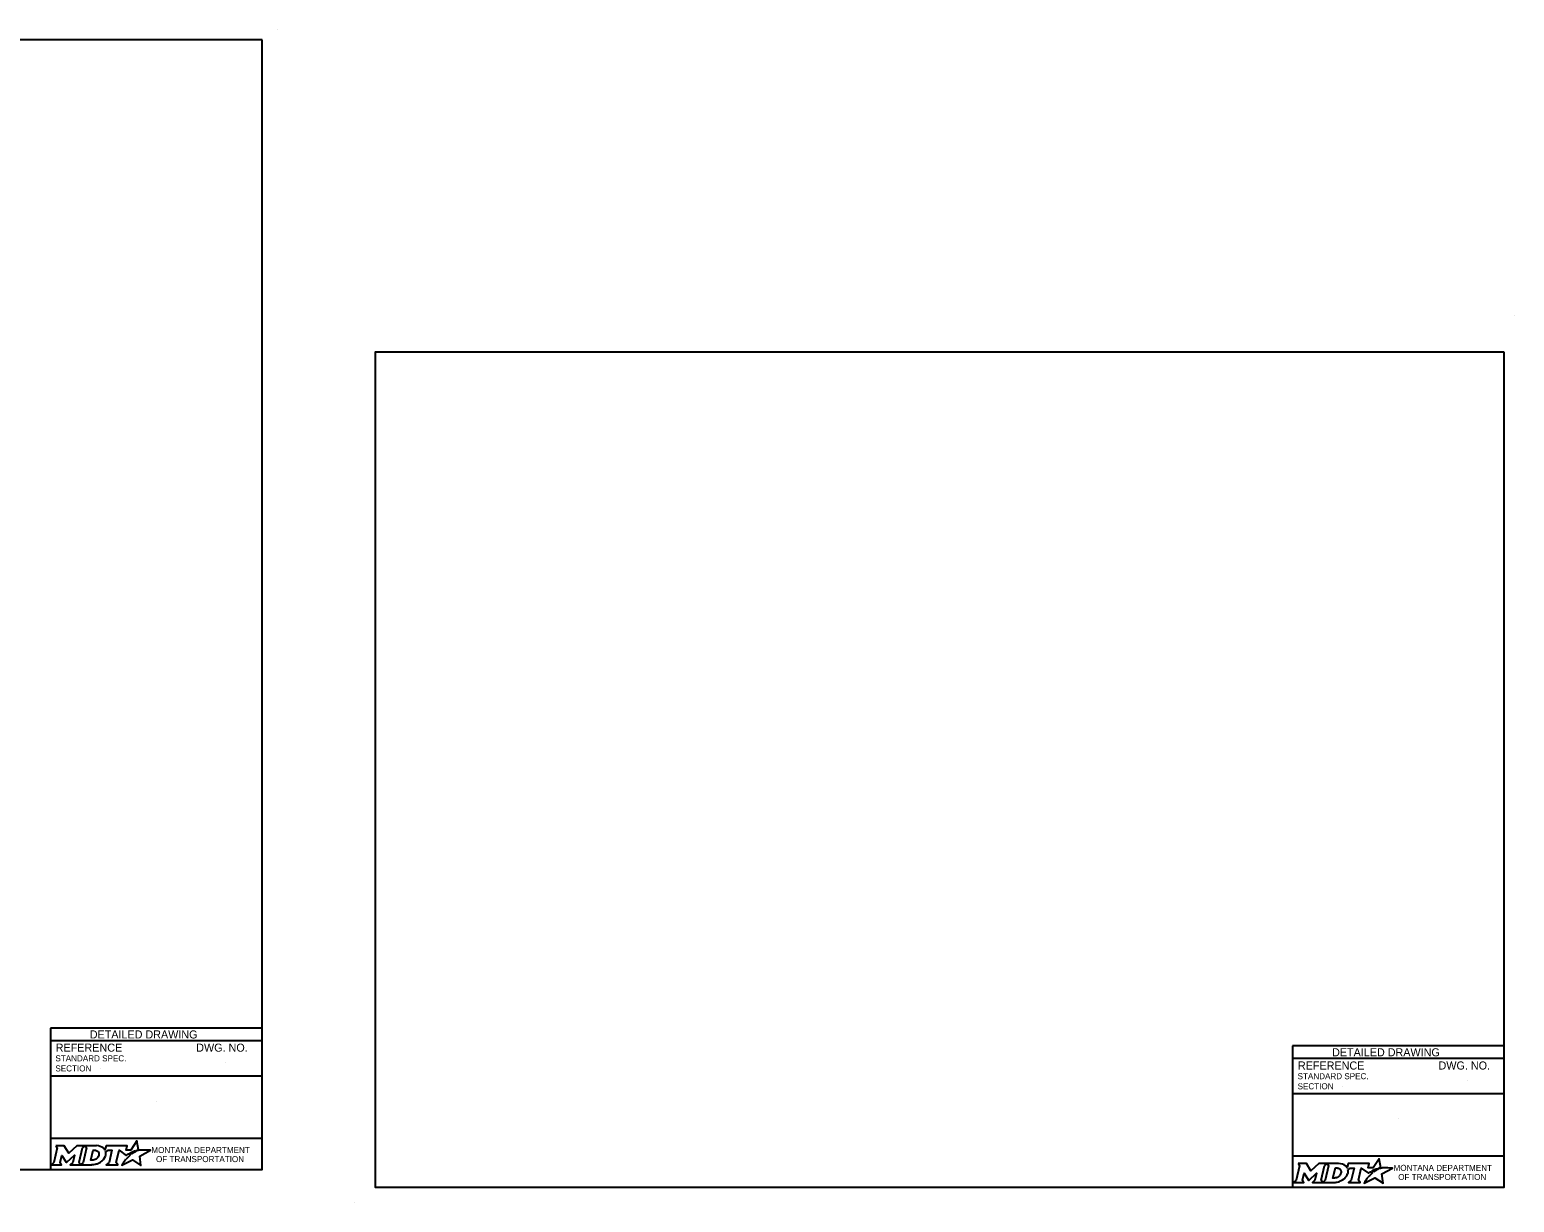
# Model space of a CAD drawing. Extents: x 49991.4 to 50021, y 49987.6 to 50011.4.
# Drawn here: x 50006.31 to 50021.04, y 49999.74 to 50011.36 of the extents above; entities that cross this region are included whole.
import ezdxf

# ---------------------------------------------------------------- set-up
doc = ezdxf.new("R2010")
doc.units = 0
for name, color, linetype in [('Default', 7, 'Continuous'), ('Level 1', 7, 'Continuous'), ('Level 2', 7, 'Continuous'), ('Level 4', 7, 'Continuous')]:
    doc.layers.add(name, color=color, linetype=linetype)

msp = doc.modelspace()

# ---------------------------------------------------------------- linework, layer by layer
at = {"layer": 'Default'}
for points in [[(50018.893, 50000.121), (50018.907, 50000.097), (50018.874, 49999.954), (50018.848, 49999.931), (50018.95, 49999.931), (50018.936, 49999.954), (50018.952, 50000.024), (50018.996, 49999.955), (50019.002, 49999.955), (50019.077, 50000.025), (50019.06, 49999.954), (50019.035, 49999.932), (50019.137, 49999.932), (50019.123, 49999.955), (50019.156, 50000.097)], [(50019.156, 50000.097), (50019.182, 50000.121), (50019.099, 50000.121), (50019.02, 50000.048), (50018.975, 50000.12), (50018.893, 50000.121)], [(50019.295, 50000.121), (50019.182, 50000.121), (50019.196, 50000.098), (50019.163, 49999.954), (50019.137, 49999.932), (50019.248, 49999.932)], [(50019.319, 50000.034), (50019.318, 50000.026), (50019.315, 50000.017), (50019.311, 50000.008), (50019.305, 50000.001), (50019.299, 49999.994), (50019.291, 49999.988), (50019.282, 49999.983), (50019.273, 49999.979), (50019.264, 49999.977), (50019.255, 49999.976), (50019.239, 49999.976), (50019.263, 50000.076), (50019.279, 50000.076), (50019.286, 50000.075), (50019.294, 50000.073), (50019.301, 50000.07), (50019.307, 50000.066), (50019.311, 50000.061), (50019.315, 50000.055), (50019.318, 50000.049), (50019.319, 50000.042), (50019.32, 50000.038), (50019.319, 50000.034)], [(50019.7, 50000.068), (50019.69, 50000.074), (50019.702, 50000.076), (50019.713, 50000.078), (50019.696, 50000.168), (50019.636, 50000.077), (50019.589, 50000.076), (50019.599, 50000.12), (50019.39, 50000.121), (50019.38, 50000.078), (50019.374, 50000.086)], [(50019.387, 50000.062), (50019.411, 50000.075), (50019.448, 50000.075), (50019.42, 49999.954), (50019.392, 49999.931), (50019.508, 49999.931), (50019.491, 49999.954), (50019.52, 50000.075), (50019.591, 50000.023), (50019.612, 50000.038), (50019.632, 50000.027)], [(50019.576, 49999.971), (50019.561, 49999.947), (50019.556, 49999.939), (50019.55, 49999.931), (50019.548, 49999.926), (50019.653, 49999.979), (50019.737, 49999.924), (50019.724, 50000.017), (50019.831, 50000.075), (50019.782, 50000.076), (50019.751, 50000.077), (50019.731, 50000.077), (50019.724, 50000.075), (50019.719, 50000.074), (50019.711, 50000.072), (50019.7, 50000.068)], [(50019.65, 50000.04), (50019.648, 50000.039), (50019.629, 50000.048), (50019.639, 50000.054), (50019.644, 50000.056), (50019.652, 50000.06), (50019.658, 50000.063), (50019.666, 50000.066), (50019.673, 50000.068), (50019.685, 50000.061), (50019.681, 50000.059), (50019.676, 50000.056), (50019.672, 50000.054), (50019.667, 50000.051), (50019.665, 50000.05), (50019.662, 50000.049), (50019.66, 50000.047), (50019.658, 50000.046), (50019.655, 50000.044), (50019.652, 50000.042), (50019.65, 50000.04)], [(50019.293, 49999.939), (50019.302, 49999.942), (50019.315, 49999.947), (50019.335, 49999.958)], [(50019.59, 49999.987), (50019.59, 49999.987)]]:
    msp.add_lwpolyline(points, dxfattribs=at)
for centre, radius, start, end in [((50019.274, 50000.059), 0.118, 300.9103, 339.1383), ((50019.319, 50000.042), 0.0709, 339.5329, 15.8582)]:
    msp.add_arc(centre, radius, start, end, dxfattribs=at)
for centre, major_axis, ratio, start_param, end_param in [((50019.293, 50000.073), (0.0834, -0.0037), 0.568097, 0.61298, 1.570796), ((50019.349, 50000.081), (0.0361, -0.0295), 0.469099, 1.225588, 1.570796), ((50019.248, 50000.08), (0, 0.148), 0.987302, 3.139398, 3.456847), ((50019.583, 49999.979), (-0.00694, -0.00806), 0.008222, 0, 3.137361), ((50019.6, 49999.997), (-0.0098, -0.0102), 0.016458, 3.141593, 6.279097), ((50019.621, 50000.017), (-0.0112, -0.0097), 0.021651, 3.157348, 6.283185)]:
    msp.add_ellipse(centre, major_axis=major_axis, ratio=ratio, start_param=start_param, end_param=end_param, dxfattribs=at)
at = {"layer": 'Level 1'}
for p, q in [((50008.765, 50011.363), (50008.765, 50011.363)), ((50021.038, 50008.524), (50021.038, 50008.524)), ((50009.537, 49999.736), (50009.537, 49999.736))]:
    msp.add_line(p, q, dxfattribs=at)
for points in [[(50008.615, 50011.263), (50000.336, 50011.263), (50000.336, 50000.062), (50008.615, 50000.062)], [(50020.938, 50008.165), (50009.737, 50008.165), (50009.737, 49999.886), (50020.938, 49999.886)]]:
    msp.add_lwpolyline(points, close=True, dxfattribs=at)
at = {"layer": 'Level 2'}
for p, q in [((50008.615, 50001.462), (50006.515, 50001.462)), ((50006.515, 50001.462), (50006.515, 50000.062)), ((50008.615, 50001.337), (50006.515, 50001.337)), ((50008.251, 50001.122), (50008.251, 50001.122)), ((50008.615, 50000.987), (50006.515, 50000.987)), ((50007.009, 50001.063), (50007.009, 50001.063)), ((50007.565, 50000.738), (50007.565, 50000.738)), ((50008.615, 50000.369), (50006.515, 50000.369))]:
    msp.add_line(p, q, dxfattribs=at)
for points in [[(50006.57, 50000.297), (50006.584, 50000.274), (50006.551, 50000.131), (50006.525, 50000.108), (50006.627, 50000.108), (50006.613, 50000.131), (50006.629, 50000.201), (50006.673, 50000.132), (50006.678, 50000.132), (50006.753, 50000.202), (50006.737, 50000.13), (50006.712, 50000.108), (50006.814, 50000.108), (50006.8, 50000.132), (50006.833, 50000.274)], [(50006.833, 50000.274), (50006.859, 50000.297), (50006.776, 50000.297), (50006.697, 50000.224), (50006.652, 50000.297), (50006.57, 50000.297)], [(50006.972, 50000.297), (50006.859, 50000.297), (50006.873, 50000.275), (50006.839, 50000.131), (50006.814, 50000.108), (50006.925, 50000.108)], [(50006.996, 50000.211), (50006.995, 50000.203), (50006.992, 50000.193), (50006.988, 50000.185), (50006.982, 50000.178), (50006.976, 50000.171), (50006.968, 50000.164), (50006.959, 50000.16), (50006.95, 50000.156), (50006.941, 50000.154), (50006.932, 50000.153), (50006.916, 50000.153), (50006.94, 50000.253), (50006.956, 50000.253), (50006.963, 50000.252), (50006.971, 50000.25), (50006.977, 50000.247), (50006.983, 50000.243), (50006.988, 50000.238), (50006.992, 50000.232), (50006.995, 50000.226), (50006.996, 50000.218), (50006.996, 50000.215), (50006.996, 50000.211)], [(50007.377, 50000.245), (50007.367, 50000.25), (50007.378, 50000.253), (50007.39, 50000.255), (50007.373, 50000.345), (50007.313, 50000.254), (50007.266, 50000.253), (50007.276, 50000.297), (50007.067, 50000.297), (50007.057, 50000.255), (50007.051, 50000.263)], [(50007.064, 50000.238), (50007.088, 50000.251), (50007.125, 50000.251), (50007.097, 50000.131), (50007.069, 50000.108), (50007.185, 50000.108), (50007.168, 50000.131), (50007.196, 50000.251), (50007.268, 50000.2), (50007.289, 50000.215), (50007.309, 50000.204)], [(50007.253, 50000.148), (50007.237, 50000.124), (50007.233, 50000.116), (50007.227, 50000.107), (50007.225, 50000.103), (50007.33, 50000.156), (50007.414, 50000.101), (50007.401, 50000.194), (50007.508, 50000.252), (50007.458, 50000.253), (50007.428, 50000.253), (50007.407, 50000.254), (50007.401, 50000.252), (50007.396, 50000.251), (50007.387, 50000.249), (50007.377, 50000.245)], [(50007.327, 50000.217), (50007.324, 50000.215), (50007.306, 50000.225), (50007.316, 50000.231), (50007.32, 50000.233), (50007.329, 50000.237), (50007.335, 50000.239), (50007.343, 50000.243), (50007.35, 50000.245), (50007.362, 50000.238), (50007.358, 50000.236), (50007.353, 50000.233), (50007.349, 50000.231), (50007.344, 50000.228), (50007.342, 50000.227), (50007.339, 50000.225), (50007.337, 50000.224), (50007.334, 50000.222), (50007.332, 50000.221), (50007.329, 50000.219), (50007.327, 50000.217)], [(50006.97, 50000.116), (50006.979, 50000.118), (50006.992, 50000.124), (50007.012, 50000.135)], [(50007.267, 50000.164), (50007.267, 50000.164)]]:
    msp.add_lwpolyline(points, dxfattribs=at)
for centre, radius, start, end in [((50006.995, 50000.219), 0.0709, 339.5329, 15.8582), ((50006.951, 50000.236), 0.118, 300.9103, 339.1383)]:
    msp.add_arc(centre, radius, start, end, dxfattribs=at)
for centre, major_axis, ratio, start_param, end_param in [((50006.97, 50000.25), (0.0834, -0.0037), 0.568097, 0.61298, 1.570796), ((50007.026, 50000.257), (0.0361, -0.0295), 0.469099, 1.225588, 1.570796), ((50006.925, 50000.257), (0, 0.148), 0.987302, 3.139398, 3.456847), ((50007.26, 50000.156), (-0.00694, -0.00806), 0.008222, 0, 3.137361), ((50007.276, 50000.174), (-0.0098, -0.0102), 0.016458, 3.141593, 6.279097), ((50007.297, 50000.194), (-0.0112, -0.0097), 0.021651, 3.157348, 6.283185)]:
    msp.add_ellipse(centre, major_axis=major_axis, ratio=ratio, start_param=start_param, end_param=end_param, dxfattribs=at)
at = {"layer": 'Level 4'}
for p, q in [((50020.938, 50001.286), (50018.838, 50001.286)), ((50018.838, 50001.286), (50018.838, 49999.886)), ((50020.938, 50001.161), (50018.838, 50001.161)), ((50020.938, 50000.811), (50018.838, 50000.811)), ((50019.332, 50000.886), (50019.332, 50000.886)), ((50020.574, 50000.946), (50020.574, 50000.946)), ((50019.888, 50000.562), (50019.888, 50000.562)), ((50020.938, 50000.193), (50018.838, 50000.193))]:
    msp.add_line(p, q, dxfattribs=at)

# ---------------------------------------------------------------- texts
at = {"layer": 'Default'}
for s, p in [('MONTANA DEPARTMENT', (50019.84, 50000.047)), ('OF TRANSPORTATION', (50019.886, 49999.957))]:
    msp.add_text(s, height=0.06, rotation=360, dxfattribs=at).set_placement(p)
at = {"layer": 'Level 2'}
for s, height, p in [('DETAILED DRAWING', 0.0799, (50006.906, 50001.36)), ('REFERENCE', 0.08, (50006.568, 50001.229)), ('DWG. NO.', 0.08, (50007.962, 50001.229)), ('STANDARD SPEC.', 0.06, (50006.565, 50001.133)), ('SECTION', 0.06, (50006.565, 50001.033))]:
    msp.add_text(s, height=height, dxfattribs=at).set_placement(p)
for s, p in [('MONTANA DEPARTMENT', (50007.517, 50000.224)), ('OF TRANSPORTATION', (50007.563, 50000.134))]:
    msp.add_text(s, height=0.06, rotation=360, dxfattribs=at).set_placement(p)
at = {"layer": 'Level 4'}
for s, height, p in [('DETAILED DRAWING', 0.0799, (50019.23, 50001.183)), ('REFERENCE', 0.08, (50018.891, 50001.052)), ('DWG. NO.', 0.08, (50020.286, 50001.052)), ('STANDARD SPEC.', 0.06, (50018.888, 50000.956)), ('SECTION', 0.06, (50018.888, 50000.856))]:
    msp.add_text(s, height=height, dxfattribs=at).set_placement(p)

doc.saveas('drawing.dxf')
